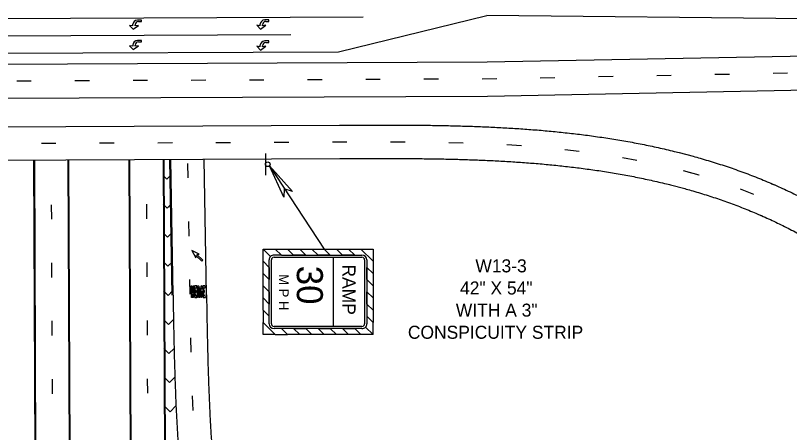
# Model space of a CAD drawing. Extents: x 582908 to 586039, y 1530940 to 1532988.
# Drawn here: x 584469 to 585300, y 1532013 to 1532461 of the extents above; entities that cross this region are included whole.
import ezdxf

# ---------------------------------------------------------------- set-up
doc = ezdxf.new("R2010")
doc.units = 0
for name, color, linetype in [('DirArrowsPavt', 7, 'Continuous'), ('LeaderLine_dp', 7, 'Continuous'), ('NonPlottingEle_dp', 7, 'Continuous'), ('PavtMessage', 7, 'Continuous'), ('PavtMisc_ep', 7, 'Continuous'), ('PMStripe18W', 7, 'Continuous'), ('PMStripe6W', 7, 'Continuous'), ('PMStripe6W(10-30)', 7, 'Continuous'), ('PMStripe6Y', 7, 'Continuous'), ('PMStripe8W', 7, 'Continuous'), ('SignPanel', 7, 'Continuous'), ('SignSupport', 7, 'Continuous'), ('TextLabel', 7, 'Continuous')]:
    doc.layers.add(name, color=color, linetype=linetype)

# ---------------------------------------------------------------- blocks, each defined once
blk = doc.blocks.new('ArrTermPnt')
at = {"layer": 'LeaderLine_dp'}
for p, q in [((-0.1, 0), (-0.12, 0.02)), ((-0.12, 0.02), (0, 0)), ((0, 0), (-0.12, -0.02)), ((-0.12, -0.02), (-0.1, 0))]:
    blk.add_line(p, q, dxfattribs=at)

msp = doc.modelspace()

# ---------------------------------------------------------------- linework, layer by layer
at = {"layer": 'DirArrowsPavt'}
for p, q in [((584658.41, 1532208.24), (584662.49, 1532200.66)), ((584666.11, 1532204.41), (584658.41, 1532208.24)), ((584662.49, 1532200.66), (584662.64, 1532203.06)), ((584662.64, 1532203.06), (584668.91, 1532196.99)), ((584663.72, 1532204.18), (584666.11, 1532204.41)), ((584669.99, 1532198.12), (584663.72, 1532204.18)), ((584668.91, 1532196.99), (584669.99, 1532198.12))]:
    msp.add_line(p, q, dxfattribs=at)
for points in [[(584600.99, 1532454.42), (584604.11, 1532454.42), (584604.11, 1532455.98), (584599.95, 1532455.99)], [(584737.77, 1532454.62), (584740.89, 1532454.61), (584740.89, 1532456.18), (584736.73, 1532456.18)], [(584594.73, 1532450.79), (584594.73, 1532449.74), (584591.21, 1532450.27), (584595.24, 1532446.1)], [(584595.24, 1532446.1), (584600.98, 1532450.25), (584597.33, 1532449.74), (584597.33, 1532450.78)], [(584731.51, 1532450.98), (584731.51, 1532449.94), (584727.99, 1532450.47), (584732.02, 1532446.29)], [(584732.02, 1532446.29), (584737.76, 1532450.45), (584734.11, 1532449.94), (584734.12, 1532450.98)], [(584601.08, 1532432.56), (584604.21, 1532432.55), (584604.21, 1532434.11), (584600.04, 1532434.12)], [(584737.77, 1532431.98), (584740.89, 1532431.98), (584740.89, 1532433.54), (584736.73, 1532433.55)], [(584594.83, 1532428.92), (584594.82, 1532427.88), (584591.31, 1532428.41), (584595.34, 1532424.23)], [(584595.34, 1532424.23), (584601.08, 1532428.39), (584597.43, 1532427.88), (584597.43, 1532428.92)], [(584731.51, 1532428.35), (584731.51, 1532427.31), (584727.99, 1532427.83), (584732.02, 1532423.66)], [(584732.02, 1532423.66), (584737.76, 1532427.82), (584734.11, 1532427.3), (584734.12, 1532428.35)]]:
    msp.add_lwpolyline(points, dxfattribs=at)
for centre, radius in [((584599.94, 1532450.78), 5.21), ((584736.72, 1532450.97), 5.21), ((584600.98, 1532450.78), 3.65), ((584737.76, 1532450.97), 3.65), ((584600.03, 1532428.91), 5.21), ((584601.08, 1532428.91), 3.65), ((584736.72, 1532428.34), 5.21), ((584737.76, 1532428.34), 3.65)]:
    msp.add_arc(centre, radius, 89.90326, 179.90326, dxfattribs=at)
at = {"layer": 'LeaderLine_dp'}
for p, q in [((584741.58, 1532299.25), (584800.41, 1532209.87)), ((584741.58, 1532299.25), (584766.27, 1532271.71)), ((584757.1, 1532265.68), (584741.58, 1532299.25)), ((584757.66, 1532274.81), (584757.1, 1532265.68)), ((584766.27, 1532271.71), (584757.66, 1532274.81))]:
    msp.add_line(p, q, dxfattribs=at)
at = {"layer": 'NonPlottingEle_dp'}
for p, q in [((584488.37, 1532305.68), (584489.76, 1531989.04)), ((584628.22, 1532306.3), (584629.61, 1531989.65)), ((584637.35, 1532160.22), (584634.8, 1532306.33))]:
    msp.add_line(p, q, dxfattribs=at)
at = {"layer": 'PavtMessage'}
for p, q in [((584657.77, 1532170.22), (584658.29, 1532170.23)), ((584657.77, 1532170.22), (584657.99, 1532157.72)), ((584657.99, 1532157.72), (584657.77, 1532170.22)), ((584658.29, 1532170.23), (584659.21, 1532162.17)), ((584659.21, 1532162.17), (584659.85, 1532170.25)), ((584659.85, 1532170.25), (584660.37, 1532170.26)), ((584660.37, 1532170.26), (584660.59, 1532157.73)), ((584663.5, 1532170.32), (584661.15, 1532170.28)), ((584661.15, 1532170.28), (584661.37, 1532157.78)), ((584661.97, 1532168.21), (584663.53, 1532168.23)), ((584662.02, 1532165.34), (584661.97, 1532168.21)), ((584662.8, 1532165.36), (584662.02, 1532165.34)), ((584662.84, 1532163.27), (584662.8, 1532165.36)), ((584663.53, 1532168.23), (584663.5, 1532170.32)), ((584664.32, 1532170.36), (584665.49, 1532170.38)), ((584664.53, 1532157.83), (584664.32, 1532170.36)), ((584665.52, 1532168.29), (584664.94, 1532168.28)), ((584664.94, 1532168.28), (584664.99, 1532165.15)), ((584664.99, 1532165.15), (584665.58, 1532165.16)), ((584666.15, 1532166.22), (584666.13, 1532167.26)), ((584666.7, 1532168.32), (584666.75, 1532165.18)), ((584668.91, 1532164.42), (584669.85, 1532164.44)), ((584668.95, 1532162.34), (584668.91, 1532164.42)), ((584669.68, 1532168.24), (584669.35, 1532166.88)), ((584672.61, 1532170.47), (584670.27, 1532170.43)), ((584670.27, 1532170.43), (584670.48, 1532157.94)), ((584671.08, 1532168.36), (584672.65, 1532168.39)), ((584671.13, 1532165.5), (584671.08, 1532168.36)), ((584671.91, 1532165.51), (584671.13, 1532165.5)), ((584671.95, 1532163.43), (584671.91, 1532165.51)), ((584672.65, 1532168.39), (584672.61, 1532170.47)), ((584658.51, 1532157.73), (584657.99, 1532157.72)), ((584659.03, 1532157.74), (584658.44, 1532161.37)), ((584658.44, 1532161.37), (584658.51, 1532157.73)), ((584659.55, 1532157.75), (584659.03, 1532157.74)), ((584660, 1532161.4), (584659.55, 1532157.75)), ((584660.07, 1532157.72), (584660, 1532161.4)), ((584660.59, 1532157.73), (584660.07, 1532157.72)), ((584661.37, 1532157.78), (584663.71, 1532157.82)), ((584662.06, 1532163.26), (584662.84, 1532163.27)), ((584662.11, 1532159.87), (584662.06, 1532163.26)), ((584663.68, 1532159.9), (584662.11, 1532159.87)), ((584663.71, 1532157.82), (584663.68, 1532159.9)), ((584665.12, 1532157.84), (584664.53, 1532157.83)), ((584665.61, 1532163.07), (584665.03, 1532163.06)), ((584665.03, 1532163.06), (584665.12, 1532157.84)), ((584666.29, 1532157.86), (584665.61, 1532163.07)), ((584666.18, 1532163.34), (584666.89, 1532157.87)), ((584666.89, 1532157.87), (584666.29, 1532157.86)), ((584669.42, 1532162.34), (584668.95, 1532162.34)), ((584670.48, 1532157.94), (584672.83, 1532157.98)), ((584671.17, 1532163.42), (584671.95, 1532163.43)), ((584671.23, 1532160.03), (584671.17, 1532163.42)), ((584672.79, 1532160.06), (584671.23, 1532160.03)), ((584672.83, 1532157.98), (584672.79, 1532160.06))]:
    msp.add_line(p, q, dxfattribs=at)
for points in [[(584667.57, 1532160.68), (584667.45, 1532167.59)], [(584667.93, 1532166.9), (584668.03, 1532161.39)], [(584669.85, 1532164.44), (584669.91, 1532160.72)], [(584669.43, 1532161.41), (584669.42, 1532162.34)]]:
    msp.add_lwpolyline(points, dxfattribs=at)
for centre, major_axis, ratio, start_param, end_param in [((584665.52, 1532168.29), (-0.04, 2.09), 0.560748, 4.712389, 6.283185), ((584665.54, 1532167.25), (-0.02, 1.04), 0.560748, 4.712389, 6.283185), ((584665.56, 1532166.21), (-0.02, 1.04), 0.560748, 3.141593, 4.712389), ((584665.58, 1532165.16), (-0.04, 2.09), 0.560748, 3.647755, 4.712389), ((584668.68, 1532164.16), (-0.11, 6.25), 0.225, 5.421015, 7.268296), ((584668.68, 1532164.16), (0.07, -4.17), 0.225, 2.279423, 3.989655), ((584668.68, 1532164.16), (-0.11, 6.25), 0.225, 2.156482, 4.126703), ((584668.68, 1532164.16), (0.07, -4.17), 0.225, 5.435123, 7.131247)]:
    msp.add_ellipse(centre, major_axis=major_axis, ratio=ratio, start_param=start_param, end_param=end_param, dxfattribs=at)
at = {"layer": 'PavtMisc_ep'}
for p, q in [((584525.87, 1532305.84), (584527.26, 1531989.2)), ((584590.72, 1532306.13), (584592.11, 1531989.49))]:
    msp.add_line(p, q, dxfattribs=at)
at = {"layer": 'PMStripe18W'}
for p, q in [((584631.57, 1532285.13), (584627.52, 1532289.15)), ((584631.57, 1532285.13), (584635.88, 1532289.47)), ((584631.91, 1532253.88), (584627.65, 1532258.1)), ((584631.91, 1532253.88), (584636.42, 1532258.42)), ((584632.25, 1532222.63), (584627.79, 1532227.06)), ((584632.25, 1532222.63), (584636.96, 1532227.38)), ((584632.59, 1532191.38), (584627.92, 1532196.01)), ((584632.59, 1532191.38), (584637.5, 1532196.33)), ((584632.93, 1532160.13), (584628.03, 1532164.99)), ((584632.93, 1532160.13), (584638.04, 1532165.28)), ((584633.29, 1532128.88), (584628.19, 1532133.95)), ((584633.29, 1532128.88), (584638.59, 1532134.23)), ((584633.73, 1532097.63), (584628.34, 1532102.98)), ((584633.73, 1532097.63), (584639.24, 1532103.2)), ((584634.29, 1532066.39), (584628.49, 1532072.13)), ((584634.29, 1532066.39), (584640.1, 1532072.25)), ((584635.01, 1532035.14), (584628.64, 1532041.45)), ((584635.01, 1532035.14), (584641.17, 1532041.36))]:
    msp.add_line(p, q, dxfattribs=at)
at = {"layer": 'PMStripe6W'}
for p, q in [((584188.62, 1532456.69), (584842.51, 1532459.59)), ((583998.86, 1532437.1), (584764.47, 1532440.5)), ((583739.97, 1532302.36), (584817.18, 1532307.14)), ((584489.16, 1532305.68), (584490.54, 1531989.04)), ((584674.06, 1532160.86), (584671.52, 1532306.49)), ((585172.62, 1532278.86), (585187.73, 1532274.87))]:
    msp.add_line(p, q, dxfattribs=at)
msp.add_arc((585125.59, 1531862.24), 407.03, 225.07112, 46.1803, dxfattribs=at)
for points in [[(584817.17, 1532307.14), (584825.62, 1532307.17), (584834.07, 1532307.21), (584842.51, 1532307.24), (584850.96, 1532307.26), (584859.41, 1532307.27), (584867.85, 1532307.27), (584876.3, 1532307.26), (584884.75, 1532307.23), (584893.2, 1532307.18), (584901.64, 1532307.11), (584910.09, 1532307.02), (584918.54, 1532306.9), (584926.99, 1532306.75), (584935.43, 1532306.57), (584943.88, 1532306.36), (584952.33, 1532306.11), (584960.77, 1532305.83), (584969.21, 1532305.5), (584977.66, 1532305.13), (584986.1, 1532304.72), (584994.53, 1532304.26), (585002.97, 1532303.75), (585011.4, 1532303.18), (585019.83, 1532302.57), (585028.25, 1532301.89), (585036.67, 1532301.16), (585045.09, 1532300.36), (585053.5, 1532299.5), (585061.9, 1532298.58), (585070.29, 1532297.59), (585078.68, 1532296.52), (585087.05, 1532295.38), (585095.42, 1532294.17), (585103.77, 1532292.88), (585112.11, 1532291.51), (585120.44, 1532290.06), (585128.76, 1532288.52), (585137.05, 1532286.9), (585145.33, 1532285.19), (585153.59, 1532283.39), (585161.83, 1532281.49), (585170.05, 1532279.5), (585172.62, 1532278.86)], [(585187.73, 1532274.87), (585194.55, 1532272.95), (585202.66, 1532270.56), (585210.74, 1532268.06), (585218.79, 1532265.46), (585226.8, 1532262.76), (585234.78, 1532259.94), (585242.71, 1532257.01), (585250.6, 1532253.96), (585258.44, 1532250.81), (585266.24, 1532247.53), (585269.58, 1532246.08)], [(585187.73, 1532274.87), (585194.55, 1532272.95), (585202.66, 1532270.56), (585210.74, 1532268.06), (585218.79, 1532265.46), (585226.8, 1532262.76), (585234.78, 1532259.94), (585242.71, 1532257.01), (585250.6, 1532253.96), (585258.44, 1532250.81), (585266.24, 1532247.53), (585273.99, 1532244.14), (585281.68, 1532240.62), (585289.32, 1532236.99), (585296.9, 1532233.24), (585304.42, 1532229.36), (585311.87, 1532225.35), (585319.25, 1532221.23), (585326.57, 1532216.97), (585333.8, 1532212.59), (585340.96, 1532208.08), (585348.04, 1532203.45), (585355.03, 1532198.68), (585361.93, 1532193.79), (585368.74, 1532188.77), (585375.45, 1532183.62), (585382.06, 1532178.33), (585388.57, 1532172.92), (585394.96, 1532167.38), (585401.25, 1532161.72), (585407.4, 1532155.93)], [(584674.06, 1532160.86), (584674.21, 1532152.42), (584674.36, 1532143.97), (584674.51, 1532135.53), (584674.67, 1532127.08), (584674.84, 1532118.64), (584675.03, 1532110.19), (584675.22, 1532101.75), (584675.44, 1532093.3), (584675.67, 1532084.86), (584675.93, 1532076.41), (584676.2, 1532067.97), (584676.51, 1532059.52), (584676.84, 1532051.08), (584677.2, 1532042.64), (584677.6, 1532034.2), (584678.03, 1532025.76), (584678.5, 1532017.33), (584679.01, 1532008.89), (584679.57, 1532000.46), (584680.16, 1531992.03), (584680.81, 1531983.61), (584681.5, 1531975.18), (584682.25, 1531966.77), (584683.05, 1531958.35), (584683.91, 1531949.95), (584684.83, 1531941.54), (584685.81, 1531933.15), (584686.85, 1531924.76), (584687.96, 1531916.38), (584689.14, 1531908.01), (584690.38, 1531899.65), (584691.7, 1531891.3), (584693.1, 1531882.97), (584694.57, 1531874.64), (584696.12, 1531866.33), (584697.76, 1531858.04), (584699.47, 1531849.76), (584701.28, 1531841.5), (584703.17, 1531833.26), (584705.15, 1531825.04), (584707.22, 1531816.85), (584709.39, 1531808.67), (584711.66, 1531800.53), (584714.02, 1531792.41), (584716.48, 1531784.32), (584719.05, 1531776.26), (584721.72, 1531768.24), (584724.49, 1531760.25), (584727.37, 1531752.3), (584730.37, 1531744.39), (584733.47, 1531736.52), (584736.68, 1531728.7), (584740.01, 1531720.93), (584743.46, 1531713.2), (584747.02, 1531705.53), (584750.7, 1531697.91), (584754.5, 1531690.36), (584758.42, 1531682.86), (584762.46, 1531675.43), (584766.63, 1531668.07), (584770.91, 1531660.78), (584775.33, 1531653.56), (584779.86, 1531646.42), (584784.53, 1531639.36), (584789.32, 1531632.39), (584794.23, 1531625.5), (584799.28, 1531618.71), (584804.45, 1531612.01), (584809.74, 1531605.42), (584815.17, 1531598.92), (584820.72, 1531592.54), (584826.4, 1531586.26), (584832.2, 1531580.1), (584838.12, 1531574.07)]]:
    msp.add_spline(points, degree=3, dxfattribs=at)
at = {"layer": 'PMStripe6W(10-30)'}
for p, q in [((585220.11, 1532397.74), (585235.73, 1532398.05)), ((585282.6, 1532398.96), (585298.22, 1532399.26)), ((584470.16, 1532390.75), (584485.79, 1532390.82)), ((584532.66, 1532391.03), (584548.28, 1532391.1)), ((584595.16, 1532391.31), (584610.78, 1532391.38)), ((584657.66, 1532391.59), (584673.28, 1532391.65)), ((584720.16, 1532391.86), (584735.78, 1532391.93)), ((584782.66, 1532392.14), (584798.28, 1532392.21)), ((584845.16, 1532392.42), (584860.78, 1532392.49)), ((584907.66, 1532392.69), (584923.28, 1532392.76)), ((584970.16, 1532392.97), (584985.78, 1532393.19)), ((585032.64, 1532394.1), (585048.27, 1532394.4)), ((585095.13, 1532395.32), (585110.75, 1532395.62)), ((585157.62, 1532396.53), (585173.24, 1532396.83)), ((584496.75, 1532323.68), (584512.38, 1532323.75)), ((584559.25, 1532323.96), (584574.88, 1532324.03)), ((584621.75, 1532324.24), (584637.38, 1532324.31)), ((584684.25, 1532324.52), (584699.88, 1532324.58)), ((584746.75, 1532324.79), (584762.37, 1532324.86)), ((584809.25, 1532325.07), (584824.87, 1532325.14)), ((584871.75, 1532325.24), (584887.37, 1532325.19)), ((584934.24, 1532324.57), (584949.86, 1532324.17)), ((584996.69, 1532322.13), (585012.29, 1532321.14)), ((585058.97, 1532316.99), (585074.49, 1532315.17)), ((585120.85, 1532308.24), (585136.21, 1532305.39)), ((584653.63, 1532302.03), (584653.9, 1532286.41)), ((585203.08, 1532289.18), (585186.35, 1532293.94)), ((585203.08, 1532289.18), (585192.22, 1532292.27)), ((585262.11, 1532268.72), (585247.55, 1532274.39)), ((585262.11, 1532268.72), (585247.55, 1532274.39)), ((584507.33, 1532257.6), (584507.4, 1532241.97)), ((584609.68, 1532258.11), (584609.75, 1532242.49)), ((584654.72, 1532239.54), (584654.99, 1532223.92)), ((584507.61, 1532195.1), (584507.68, 1532179.47)), ((584609.96, 1532195.61), (584610.02, 1532179.99)), ((584655.81, 1532177.05), (584656.08, 1532161.43)), ((584507.88, 1532132.6), (584507.95, 1532116.97)), ((584610.23, 1532133.11), (584610.3, 1532117.49)), ((584656.96, 1532114.56), (584657.32, 1532098.94)), ((584508.15, 1532070.1), (584508.22, 1532054.47)), ((584610.5, 1532070.61), (584610.57, 1532054.99)), ((584658.82, 1532052.09), (584659.5, 1532036.48))]:
    msp.add_line(p, q, dxfattribs=at)
at = {"layer": 'PMStripe6Y'}
for p, q in [((584815.89, 1532421.97), (584975.13, 1532460.94)), ((585444.1, 1532456.01), (584975.33, 1532460.96)), ((583918.07, 1532417.99), (584815.89, 1532421.97)), ((584975.55, 1532410.96), (585444.26, 1532420.07)), ((583847.49, 1532405.96), (584975.54, 1532410.96)), ((583809.79, 1532338.61), (584817.02, 1532343.07)), ((584525.09, 1532305.84), (584526.48, 1531989.2)), ((584591.5, 1532306.13), (584592.89, 1531989.49)), ((585181.6, 1532313.66), (585196.71, 1532309.67))]:
    msp.add_line(p, q, dxfattribs=at)
msp.add_arc((585125.59, 1531862.24), 442.97, 225.02103, 46.23038, dxfattribs=at)
for points in [[(584817.02, 1532343.07), (584825.47, 1532343.11), (584833.93, 1532343.14), (584842.4, 1532343.17), (584850.88, 1532343.2), (584859.38, 1532343.21), (584867.88, 1532343.21), (584876.39, 1532343.2), (584884.91, 1532343.17), (584893.45, 1532343.12), (584901.99, 1532343.05), (584910.54, 1532342.96), (584919.11, 1532342.83), (584927.68, 1532342.68), (584936.27, 1532342.5), (584944.86, 1532342.29), (584953.46, 1532342.03), (584962.07, 1532341.74), (584970.69, 1532341.41), (584979.32, 1532341.03), (584987.96, 1532340.61), (584996.6, 1532340.14), (585005.25, 1532339.61), (585013.91, 1532339.03), (585022.58, 1532338.4), (585031.25, 1532337.7), (585039.92, 1532336.95), (585048.6, 1532336.13), (585057.29, 1532335.24), (585065.98, 1532334.28), (585074.67, 1532333.26), (585083.36, 1532332.15), (585092.05, 1532330.97), (585100.74, 1532329.71), (585109.43, 1532328.37), (585118.11, 1532326.94), (585126.79, 1532325.43), (585135.47, 1532323.83), (585144.14, 1532322.13), (585152.8, 1532320.34), (585161.45, 1532318.46), (585170.09, 1532316.47), (585178.71, 1532314.38), (585181.6, 1532313.66)], [(585196.71, 1532309.67), (585204.49, 1532307.48), (585213.04, 1532304.97), (585221.57, 1532302.33), (585230.07, 1532299.59), (585238.55, 1532296.72), (585246.99, 1532293.74), (585255.4, 1532290.63), (585263.78, 1532287.4), (585272.11, 1532284.04), (585280.41, 1532280.56), (585283.96, 1532279.02)], [(585196.71, 1532309.67), (585204.49, 1532307.48), (585213.04, 1532304.97), (585221.57, 1532302.33), (585230.07, 1532299.59), (585238.55, 1532296.72), (585246.99, 1532293.74), (585255.4, 1532290.63), (585263.78, 1532287.4), (585272.11, 1532284.04), (585280.41, 1532280.56), (585288.66, 1532276.94), (585296.87, 1532273.2), (585305.02, 1532269.32), (585313.12, 1532265.31), (585321.16, 1532261.16), (585329.14, 1532256.87), (585337.06, 1532252.45), (585344.91, 1532247.88), (585352.68, 1532243.17), (585360.38, 1532238.32), (585368.01, 1532233.33), (585375.54, 1532228.19), (585382.99, 1532222.91), (585390.35, 1532217.48), (585397.61, 1532211.91), (585404.77, 1532206.19), (585411.82, 1532200.32), (585418.76, 1532194.31), (585425.59, 1532188.15), (585432.02, 1532182.11)]]:
    msp.add_spline(points, degree=3, dxfattribs=at)
at = {"layer": 'PMStripe8W'}
for p, q in [((584975.98, 1532374.25), (585444.98, 1532383.36)), ((583832.01, 1532369.18), (584975.98, 1532374.25)), ((584627.44, 1532306.29), (584628.82, 1531989.65)), ((584638.13, 1532160.23), (584635.58, 1532306.33))]:
    msp.add_line(p, q, dxfattribs=at)
msp.add_spline([(584638.13, 1532160.23), (584638.28, 1532151.78), (584638.43, 1532143.32), (584638.58, 1532134.85), (584638.74, 1532126.37), (584638.91, 1532117.88), (584639.1, 1532109.38), (584639.3, 1532100.87), (584639.51, 1532092.35), (584639.75, 1532083.82), (584640.01, 1532075.28), (584640.29, 1532066.73), (584640.6, 1532058.17), (584640.93, 1532049.6), (584641.3, 1532041.03), (584641.71, 1532032.44), (584642.15, 1532023.84), (584642.63, 1532015.24), (584643.15, 1532006.63), (584643.71, 1531998.01), (584644.32, 1531989.39), (584644.98, 1531980.76), (584645.7, 1531972.12), (584646.47, 1531963.47), (584647.29, 1531954.82), (584648.17, 1531946.17), (584649.12, 1531937.51), (584650.13, 1531928.85), (584651.2, 1531920.19), (584652.35, 1531911.52), (584653.57, 1531902.86), (584654.86, 1531894.19), (584656.23, 1531885.53), (584657.3, 1531879.08)], degree=3, dxfattribs=at)
at = {"layer": 'SignPanel'}
for p, q in [((584734.78, 1532144.24), (584734.78, 1532209.87)), ((584747.91, 1532209.87), (584852.91, 1532209.87)), ((584767.59, 1532203.31), (584761.03, 1532209.87)), ((584780.72, 1532203.31), (584774.16, 1532209.87)), ((584793.84, 1532203.31), (584787.28, 1532209.87)), ((584806.97, 1532203.31), (584800.41, 1532209.87)), ((584820.09, 1532203.31), (584813.53, 1532209.87)), ((584833.22, 1532203.31), (584826.66, 1532209.87)), ((584852.91, 1532196.74), (584839.78, 1532209.87)), ((584852.91, 1532209.87), (584852.91, 1532131.12)), ((584741.34, 1532137.68), (584741.34, 1532198.39)), ((584743.75, 1532129.48), (584743.75, 1532198.39)), ((584746.59, 1532201.05), (584841.09, 1532201.05)), ((584754.47, 1532203.31), (584841.09, 1532203.31)), ((584810.25, 1532201.05), (584810.25, 1532126.81)), ((584843.94, 1532198.39), (584843.94, 1532129.48)), ((584846.34, 1532198.39), (584846.34, 1532137.68)), ((584741.34, 1532190.18), (584734.78, 1532196.74)), ((584852.91, 1532183.62), (584846.34, 1532190.18)), ((584741.34, 1532177.06), (584734.78, 1532183.62)), ((584852.91, 1532170.49), (584846.34, 1532177.06)), ((584741.34, 1532163.93), (584734.78, 1532170.49)), ((584741.34, 1532150.81), (584734.78, 1532157.37)), ((584852.91, 1532157.37), (584846.34, 1532163.93)), ((584852.91, 1532144.24), (584846.34, 1532150.81)), ((584734.78, 1532117.99), (584734.78, 1532131.12)), ((584841.09, 1532126.81), (584746.59, 1532126.81)), ((584841.09, 1532124.56), (584754.47, 1532124.56)), ((584774.16, 1532117.99), (584767.59, 1532124.56)), ((584787.28, 1532117.99), (584780.72, 1532124.56)), ((584800.41, 1532117.99), (584793.84, 1532124.56)), ((584813.53, 1532117.99), (584806.97, 1532124.56)), ((584826.66, 1532117.99), (584820.09, 1532124.56)), ((584839.78, 1532117.99), (584833.22, 1532124.56)), ((584844.86, 1532126.05), (584852.91, 1532117.99)), ((584747.91, 1532117.99), (584734.78, 1532117.99)), ((584852.91, 1532117.99), (584761.03, 1532117.99))]:
    msp.add_line(p, q, dxfattribs=at)
for points in [[(584742.83, 1532201.82), (584734.78, 1532209.87), (584747.91, 1532209.87)], [(584747.91, 1532209.87), (584754.47, 1532203.31), (584746.59, 1532203.31)], [(584741.34, 1532129.48), (584741.34, 1532137.68), (584734.78, 1532144.24), (584734.78, 1532131.12), (584747.91, 1532117.99), (584761.03, 1532117.99)], [(584852.91, 1532117.99), (584852.91, 1532131.12), (584846.34, 1532137.68), (584846.34, 1532129.48)], [(584761.03, 1532117.99), (584754.47, 1532124.56), (584746.59, 1532124.56)]]:
    msp.add_lwpolyline(points, dxfattribs=at)
for points in [[(584774.16, 1532209.87), (584780.72, 1532203.31), (584767.59, 1532203.31), (584761.03, 1532209.87)], [(584787.28, 1532209.87), (584800.41, 1532209.87), (584806.97, 1532203.31), (584793.84, 1532203.31)], [(584813.53, 1532209.87), (584826.66, 1532209.87), (584833.22, 1532203.31), (584820.09, 1532203.31)], [(584852.91, 1532209.87), (584852.91, 1532196.74), (584839.78, 1532209.87)], [(584741.34, 1532190.18), (584741.34, 1532177.06), (584734.78, 1532183.62), (584734.78, 1532196.74)], [(584846.34, 1532190.18), (584852.91, 1532183.62), (584852.91, 1532170.49), (584846.34, 1532177.06)], [(584734.78, 1532170.49), (584741.34, 1532163.93), (584741.34, 1532150.81), (584734.78, 1532157.37)], [(584846.34, 1532163.93), (584852.91, 1532157.37), (584852.91, 1532144.24), (584846.34, 1532150.81)], [(584780.72, 1532124.56), (584787.28, 1532117.99), (584774.16, 1532117.99), (584767.59, 1532124.56)], [(584806.97, 1532124.56), (584813.53, 1532117.99), (584800.41, 1532117.99), (584793.84, 1532124.56)], [(584833.22, 1532124.56), (584839.78, 1532117.99), (584826.66, 1532117.99), (584820.09, 1532124.56)]]:
    msp.add_lwpolyline(points, close=True, dxfattribs=at)
for centre, major_axis, start_param, end_param in [((584746.59, 1532198.39), (-5.25, 0), 5.511152, 6.283185), ((584746.59, 1532198.39), (-5.25, 0), 4.712389, 5.511152), ((584746.59, 1532198.39), (-2.84, 0), 4.712389, 6.283185), ((584841.09, 1532198.39), (-5.25, 0), 3.141593, 4.712389), ((584841.09, 1532198.39), (-2.84, 0), 3.141593, 4.712389), ((584746.59, 1532129.48), (5.25, 0), 3.141593, 4.712389), ((584746.59, 1532129.48), (2.84, 0), 3.141593, 4.712389), ((584841.09, 1532129.48), (2.84, 0), 4.712389, 6.283185), ((584841.09, 1532129.48), (5.25, 0), 4.712389, 5.511152), ((584841.09, 1532129.48), (5.25, 0), 5.511152, 6.283185)]:
    msp.add_ellipse(centre, major_axis=major_axis, ratio=0.9375, start_param=start_param, end_param=end_param, dxfattribs=at)
at = {"layer": 'SignSupport'}
msp.add_line((584737.36, 1532312.66), (584737.29, 1532289.39), dxfattribs=at)
msp.add_circle((584739.82, 1532301.02), 2.49, dxfattribs=at)

# ---------------------------------------------------------------- block references
at = {"layer": 'TextLabel', "xscale": 2.041666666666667, "yscale": 1.9442318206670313, "rotation": 123.35314051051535}
msp.add_blockref('ArrTermPnt', (584741.58, 1532299.25), dxfattribs=at)

# ---------------------------------------------------------------- texts
at = {"layer": 'SignPanel'}
for s, height, p in [('30', 27.992, (584771.08, 1532192.01)), ('RAMP', 14.006, (584820.14, 1532193.33)), ('M P H', 10.499, (584751.76, 1532182.96))]:
    msp.add_text(s, height=height, rotation=270, dxfattribs=at).set_placement(p)
at = {"layer": 'TextLabel'}
for s, p in [('W13-3', (584962.89, 1532184.88)), ('42" X 54"', (584946.42, 1532161.08)), ('WITH A 3" ', (584941.89, 1532137.28)), ('CONSPICUITY STRIP', (584890.39, 1532113.48))]:
    msp.add_text(s, height=14, dxfattribs=at).set_placement(p)

doc.saveas('drawing.dxf')
